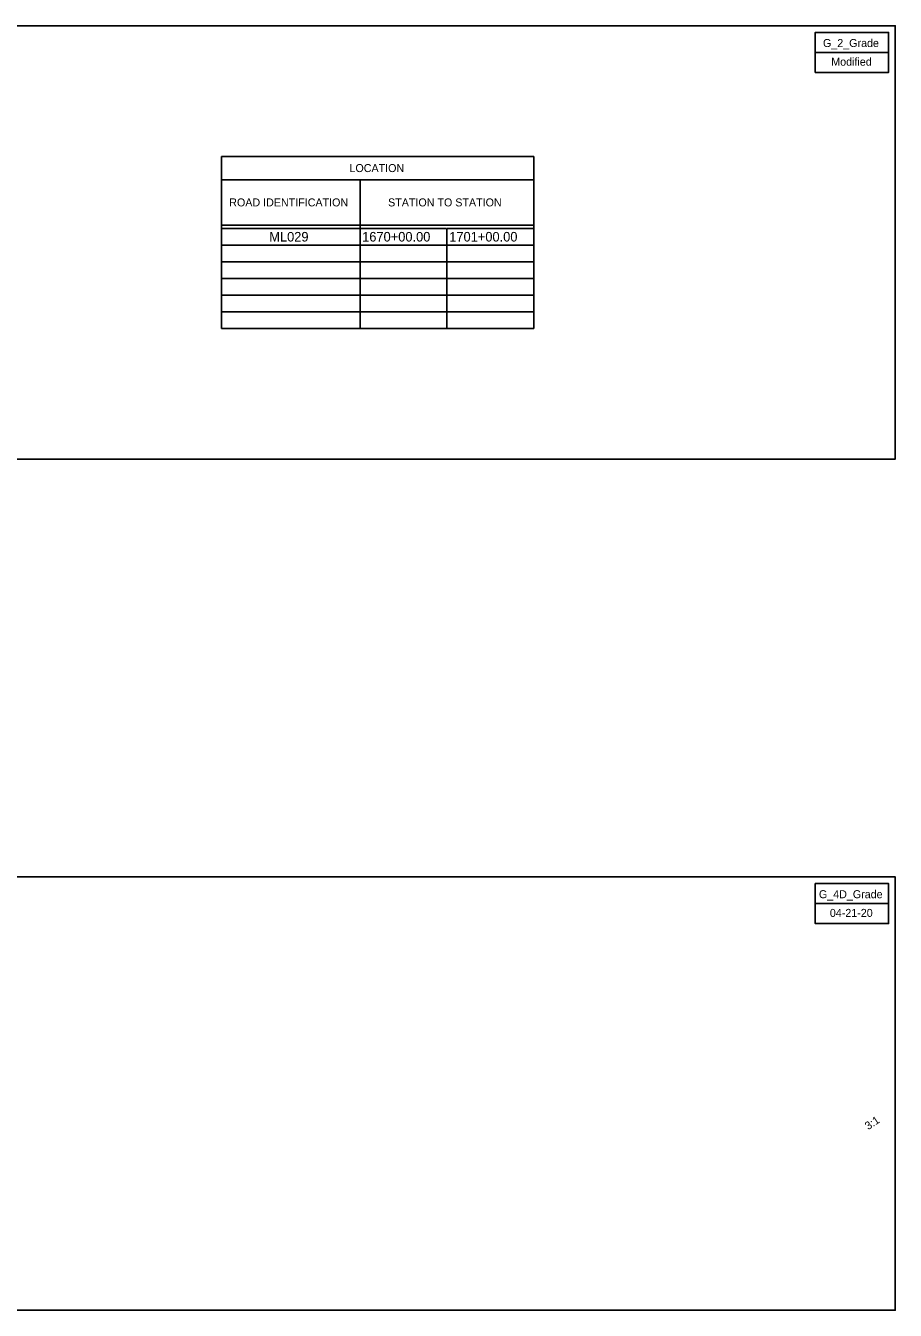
# Model space of a CAD drawing. Extents: x 4574 to 81668, y 5908 to 13780.
# Drawn here: x 11949 to 13253, y 5908 to 7834 of the extents above; entities that cross this region are included whole.
import ezdxf

# ---------------------------------------------------------------- set-up
doc = ezdxf.new("R2010")
doc.units = 0
for name, color, linetype in [('dsnStdBorder', 7, 'Continuous'), ('dsnStdLabel', 7, 'Continuous'), ('dsnStdTable', 7, 'Continuous'), ('dsnTextTabulation', 7, 'Continuous'), ('SheetBorder', 7, 'Continuous')]:
    doc.layers.add(name, color=color, linetype=linetype)

msp = doc.modelspace()

# ---------------------------------------------------------------- linework, layer by layer
at = {"layer": 'dsnStdBorder'}
for points in [[(10147.5, 7834), (13252.5, 7834), (13252.5, 7184), (10147.5, 7184), (10147.5, 7834)], [(13242.5, 7824), (13242.5, 7764), (13132.5, 7764), (13132.5, 7824), (13242.5, 7824), (13242.5, 7794), (13132.5, 7794)], [(10147.5, 6557.5), (13252.5, 6557.5), (13252.5, 5907.5), (10147.5, 5907.5), (10147.5, 6557.5)], [(13242.5, 6547.5), (13242.5, 6487.5), (13132.5, 6487.5), (13132.5, 6547.5), (13242.5, 6547.5), (13242.5, 6517.5), (13132.5, 6517.5)]]:
    msp.add_lwpolyline(points, dxfattribs=at)
at = {"layer": 'dsnStdTable'}
for p, q in [((12242.3, 7638), (12710.3, 7638)), ((12242.3, 7380), (12242.3, 7638)), ((12710.3, 7530), (12710.3, 7638)), ((12242.3, 7603), (12710.3, 7603)), ((12450.3, 7380), (12450.3, 7603)), ((12242.3, 7535), (12710.3, 7535)), ((12242.3, 7530), (12450.3, 7530)), ((12450.3, 7530), (12579.3, 7530)), ((12580.3, 7380), (12580.3, 7530)), ((12580.3, 7530), (12710.3, 7530)), ((12710.3, 7505), (12710.3, 7530)), ((12242.3, 7505), (12710.3, 7505)), ((12710.3, 7380), (12710.3, 7505)), ((12242.3, 7480), (12710.3, 7480)), ((12242.3, 7455), (12710.3, 7455)), ((12242.3, 7430), (12710.3, 7430)), ((12242.3, 7405), (12710.3, 7405)), ((12242.3, 7380), (12710.3, 7380))]:
    msp.add_line(p, q, dxfattribs=at)

# ---------------------------------------------------------------- texts
at = {"layer": 'dsnStdLabel'}
msp.add_text('3:1', height=12, rotation=33.6874, dxfattribs=at).set_placement((13211.8, 6177.5))
at = {"layer": 'dsnStdTable'}
for s, p in [('LOCATION', (12434.1, 7614.5)), ('ROAD IDENTIFICATION', (12253.8, 7563)), ('STATION TO STATION', (12492, 7563))]:
    msp.add_text(s, height=12, dxfattribs=at).set_placement(p)
at = {"layer": 'dsnTextTabulation'}
for s, p in [('G_2_Grade', (13144.1, 7802)), ('Modified', (13156.5, 7774)), ('G_4D_Grade', (13138, 6525.5)), ('04-21-20', (13154.4, 6497.5))]:
    msp.add_text(s, height=12, dxfattribs=at).set_placement(p)
at = {"layer": 'SheetBorder'}
for s, p in [('ML029', (12313.8, 7510.3)), ('1670+00.00', (12453.1, 7510.3)), ('1701+00.00', (12583.7, 7510.3))]:
    msp.add_text(s, height=14.4, dxfattribs=at).set_placement(p)

doc.saveas('drawing.dxf')
